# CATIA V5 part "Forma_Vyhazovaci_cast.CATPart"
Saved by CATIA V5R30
Part number: Forma_Vyhazovaci_cast
Publications: "__DrillHole_Ejector_E1710_2.1_", "__DrillHole_Ejector_E1710_3.1_", "__DrillHole_Ejector_E1710_4.1_", "__DrillHole_Ejector_E1710_5.1_", "__DrillHole_Ejector_E1710_6.1_", "__DrillHole_Ejector_E1710_7.1_", "__DrillHole_Ejector_E1710_8.1_", "__DrillHole_Ejector_E1710_9.1_", "__DrillHole_Ejector_E1710_10.1_", "__DrillHole_Ejector_E1710_11.1_", "__DrillHole_Ejector_E1710_1.1_", "__DrillHole_Ejector_E1710_13.1_", "__DrillHole_Ejector_E1710_14.1_", "__DrillHole_Ejector_E1710_15.1_", "__DrillHole_Ejector_E1710_16.1_", "__DrillHole_Ejector_E1710_17.1_", "__DrillHole_Ejector_E1710_18.1_", "__DrillHole_Ejector_E1710_19.1_", "__DrillHole_Ejector_E1710_20.1_", "__DrillHole_Ejector_E1710_21.1_", "__DrillHole_Ejector_E1710_23.1_", "__DrillHole_Ejector_E1710_24.1_", "__DrillHole_Ejector_E1710_25.1_", "__DrillHole_Ejector_E1710_26.1_", "__DrillHole_Ejector_E1710_27.1_", "__DrillHole_Ejector_E1710_28.1_", "__DrillHole_Ejector_E1710_29.1_", "__DrillHole_Ejector_E1710_31.1_", "__DrillHole_Ejector_E1710_32.1_", "__DrillHole_Ejector_E1710_33.1_", "__DrillHole_Ejector_E1710_34.1_", "__DrillHole_Ejector_E1710_35.1_", "__DrillHole_Ejector_E1710_36.1_", "__DrillHole_Ejector_E1710_37.1_", "TapHole_CapScrew_E1200_4.1_", "TapHole_CapScrew_E1200_4.2_", "TapHole_CapScrew_E1200_2.1_", "TapHole_CapScrew_E1200_2.2_", "TapHole_CapScrew_E1200_1.1_", "TapHole_CapScrew_E1200_1.2_", "__DrillHole_Ejector_E1710_1.2_", "__DrillHole_Ejector_E1710_2.2_", "__DrillHole_Ejector_E1710_3.2_", "__DrillHole_Ejector_E1710_4.2_"
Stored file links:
  E:\Bakalarka\Model\Forma_v7\Forma_Vyhazovaci_cast.CATPart
  E:\Bakalarka\Model\Forma_v7\Forma.CATProduct
  E:\Bakalarka\Model\Forma_v7\TlgItf_Vyhazovaci_cast.CATProduct
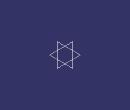
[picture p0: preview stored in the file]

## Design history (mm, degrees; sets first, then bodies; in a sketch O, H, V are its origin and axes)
Body1 (main body)
Body2 "__DrillHole"
  Solid1: linked copy from another document
Body3 "__DrillHole"
  Solid2: linked copy from another document
Body4 "__DrillHole"
  Solid3: linked copy from another document
Body5 "__DrillHole"
  Solid4: linked copy from another document
Body6 "__DrillHole"
  Solid5: linked copy from another document
Body7 "__DrillHole"
  Solid6: linked copy from another document
Body8 "__DrillHole"
  Solid7: linked copy from another document
Body9 "__DrillHole"
  Solid8: linked copy from another document
Body10 "__DrillHole"
  Solid9: linked copy from another document
Body11 "__DrillHole"
  Solid10: linked copy from another document
Body12 "__DrillHole"
  Solid11: linked copy from another document
Body13 "__DrillHole"
  Solid12: linked copy from another document
Body14 "__DrillHole"
  Solid13: linked copy from another document
Body15 "__DrillHole"
  Solid14: linked copy from another document
Body16 "__DrillHole"
  Solid15: linked copy from another document
Body17 "__DrillHole"
  Solid16: linked copy from another document
Body18 "__DrillHole"
  Solid17: linked copy from another document
Body19 "__DrillHole"
  Solid18: linked copy from another document
Body20 "__DrillHole"
  Solid19: linked copy from another document
Body21 "__DrillHole"
  Solid20: linked copy from another document
Body22 "__DrillHole"
  Solid21: linked copy from another document
Body23 "__DrillHole"
  Solid22: linked copy from another document
Body24 "__DrillHole"
  Solid23: linked copy from another document
Body25 "__DrillHole"
  Solid24: linked copy from another document
Body26 "__DrillHole"
  Solid25: linked copy from another document
Body27 "__DrillHole"
  Solid26: linked copy from another document
Body28 "__DrillHole"
  Solid27: linked copy from another document
Body29 "__DrillHole"
  Solid28: linked copy from another document
Body30 "__DrillHole"
  Solid29: linked copy from another document
Body31 "__DrillHole"
  Solid30: linked copy from another document
Body32 "__DrillHole"
  Solid31: linked copy from another document
Body33 "__DrillHole"
  Solid32: linked copy from another document
Body34 "__DrillHole"
  Solid33: linked copy from another document
Body35 "__DrillHole"
  Solid34: linked copy from another document
Body36 "TapHole"
  Solid35: linked copy from another document
Body37 "TapHole"
  Solid36: linked copy from another document
Body38 "TapHole"
  Solid37: linked copy from another document
Body39 "TapHole"
  Solid38: linked copy from another document
Body40 "TapHole"
  Solid39: linked copy from another document
Body41 "TapHole"
  Solid40: linked copy from another document
Body42 "__DrillHole"
  Solid41: linked copy from another document
Body43 "__DrillHole"
  Solid42: linked copy from another document
Body44 "__DrillHole"
  Solid43: linked copy from another document
Body45 "__DrillHole"
  Solid44: linked copy from another document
